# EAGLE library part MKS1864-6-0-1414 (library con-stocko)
Serie MKS 1850 Lötstifte In-line, Raster 2.5 mm, Stiftwannen, stehend, mit Rastlasche Source: http://www.stocko.de/de/index.php?seite=ka_rfk2_mks1850.html&rubrik=Katalog+-+RFK+2 rfk_1850.pdf
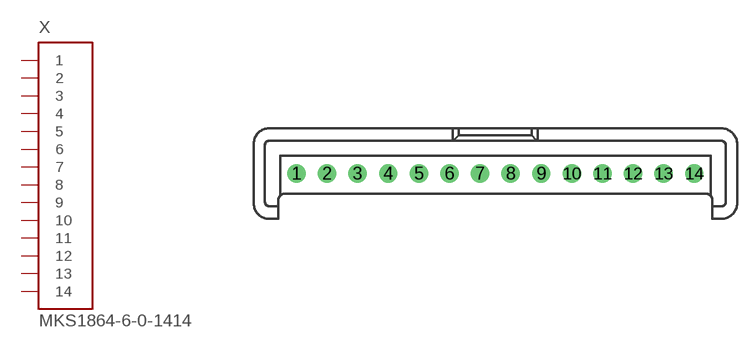
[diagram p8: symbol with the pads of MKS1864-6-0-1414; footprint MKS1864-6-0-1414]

Designator prefix X

## MKS1864-6-0-1414 (OC_FARNELL: unknown; OC_NEWARK: unknown)  [MKS1864-6-0-1414]
1  1  in
2  2  in
3  3  in
4  4  in
5  5  in
6  6  in
7  7  in
8  8  in
9  9  in
10  10  in
11  11  in
12  12  in
13  13  in
14  14  in

## Footprint MKS1864-6-0-1414 (pad centres in mm)
Serie MKS 1850 Lötstifte In-line, Raster 2.5 mm, Stiftwannen, stehend, mit Rastlasche Source: http://www.stocko.de/de/index.php?seite=ka_rfk2_mks1850.html&rubrik=Katalog+-+RFK+2 rfk_1850.pdf
drill 1 pad 1.422 round: 1 -16.25,0; 2 -13.75,0; 3 -11.25,0; 4 -8.75,0; 5 -6.25,0; 6 -3.75,0; 7 -1.25,0; 8 1.25,0; 9 3.75,0; 10 6.25,0; 11 8.75,0; 12 11.25,0; 13 13.75,0; 14 16.25,0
